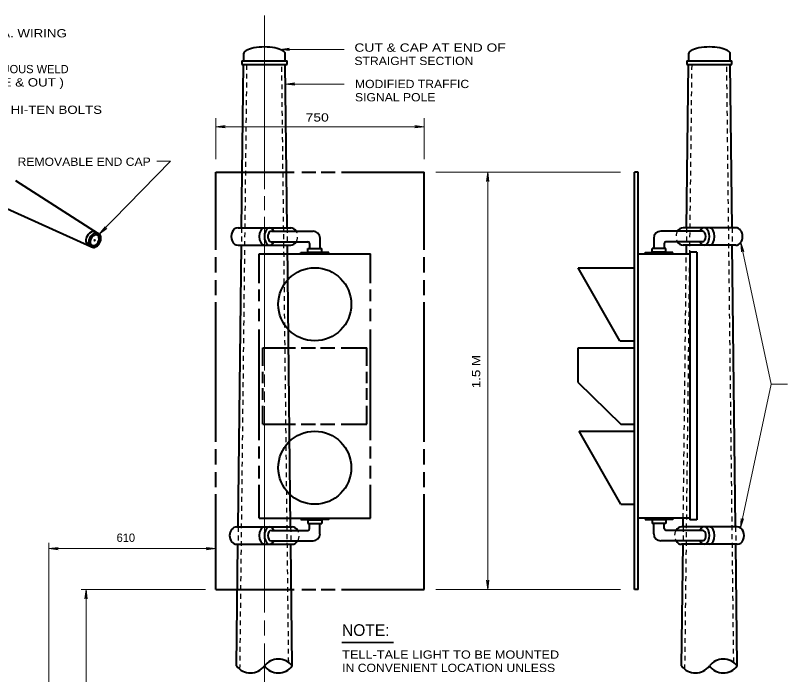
# Model space of a CAD drawing. Extents: x 312583 to 312854, y 144419 to 144597.
# Drawn here: x 312673.4 to 312744.4, y 144484.2 to 144544.7 of the extents above; entities that cross this region are included whole.
import ezdxf
from ezdxf.enums import TextEntityAlignment as Align

# ---------------------------------------------------------------- set-up
doc = ezdxf.new("R2010")
doc.units = 0
doc.header["$LTSCALE"] = 0.3
doc.header["$PDMODE"] = 32
doc.header["$PDSIZE"] = 0.15
doc.linetypes.add('SHORT_DASHED', pattern=[2.7, 1.5, -1.2])
doc.layers.add('1', color=7, linetype='Continuous', lineweight=40)
doc.layers.add('2', color=7, linetype='Continuous', lineweight=13)

msp = doc.modelspace()

# ---------------------------------------------------------------- linework, layer by layer
at = {"layer": '1', "lineweight": 13}
for p, q in [((312696.2997, 144544.7226), (312696.2997, 144528.7529)), ((312696.2997, 144528.1243), (312696.2997, 144526.8516)), ((312696.2997, 144526.2153), (312696.2997, 144512.1009)), ((312696.2997, 144511.7329), (312696.2997, 144510.6136)), ((312696.2997, 144510.1843), (312696.2997, 144509.2106)), ((312696.2997, 144508.8196), (312696.2997, 144489.8829)), ((312696.2997, 144489.1469), (312696.2997, 144487.7593)), ((312696.2997, 144487.0309), (312696.2997, 144467.6036))]:
    msp.add_line(p, q, dxfattribs=at)
at = {"layer": '1', "linetype": 'SHORT_DASHED', "lineweight": 25}
for p, q in [((312694.0533, 144484.6543), (312694.6973, 144540.2299)), ((312698.5307, 144485.2906), (312697.8943, 144540.2299)), ((312734.9397, 144484.6543), (312735.5913, 144540.2299)), ((312739.4247, 144485.2906), (312738.7807, 144540.2299)), ((312694.2067, 144525.2186), (312694.1913, 144523.6239)), ((312698.385, 144525.2186), (312698.408, 144523.6239)), ((312735.093, 144525.2186), (312735.0777, 144523.6239)), ((312739.279, 144525.2186), (312739.2943, 144523.6239)), ((312734.7863, 144498.5463), (312735.07, 144522.8189)), ((312693.8923, 144497.7489), (312693.8693, 144496.1466)), ((312698.707, 144497.7489), (312698.7223, 144496.1466)), ((312734.7787, 144497.7489), (312734.7633, 144496.1466)), ((312739.5933, 144497.7489), (312739.6163, 144496.1466))]:
    msp.add_line(p, q, dxfattribs=at)
at = {"layer": '1'}
for p, q in [((312694.2067, 144525.2186), (312694.383, 144540.2299)), ((312694.222, 144540.5519), (312698.3773, 144540.5519)), ((312694.222, 144540.2299), (312698.3773, 144540.2299)), ((312698.385, 144525.2186), (312698.2163, 144540.2299)), ((312735.093, 144525.2186), (312735.2693, 144540.2299)), ((312735.1083, 144540.5519), (312739.2637, 144540.5519)), ((312735.1083, 144540.2299), (312739.2637, 144540.2299)), ((312739.279, 144525.2186), (312739.1027, 144540.2299)), ((312691.8223, 144523.1793), (312691.8223, 144530.3323)), ((312691.8223, 144530.3323), (312699.0367, 144530.3323)), ((312699.7343, 144530.3323), (312701.0223, 144530.3323)), ((312701.513, 144530.3323), (312702.801, 144530.3323)), ((312703.3913, 144530.3323), (312710.989, 144530.3323)), ((312710.989, 144523.1793), (312710.989, 144530.3323)), ((312730.3167, 144491.9989), (312730.3167, 144530.3323)), ((312730.6387, 144530.3323), (312730.3167, 144530.3323)), ((312730.3167, 144491.9989), (312730.3167, 144530.3323)), ((312730.6387, 144491.9989), (312730.6387, 144530.3323)), ((312673.4223, 144529.5579), (312681.0353, 144524.6819)), ((312671.9733, 144527.2656), (312680.3377, 144523.5013)), ((312693.877, 144525.2186), (312698.7147, 144525.2186)), ((312696.936, 144524.8966), (312700.7693, 144524.8966)), ((312736.5497, 144524.8966), (312732.7163, 144524.8966)), ((312739.6087, 144525.2186), (312734.771, 144525.2186)), ((312696.936, 144523.9383), (312700.294, 144523.9383)), ((312701.4057, 144524.2603), (312701.4057, 144523.3019)), ((312732.0723, 144524.2603), (312732.0723, 144523.3019)), ((312736.5497, 144523.9383), (312733.1917, 144523.9383)), ((312693.877, 144523.6239), (312698.7147, 144523.6239)), ((312693.8923, 144497.7489), (312694.1913, 144523.6239)), ((312698.707, 144497.7489), (312698.408, 144523.6239)), ((312700.294, 144523.3019), (312701.5667, 144523.3019)), ((312700.294, 144522.9799), (312700.294, 144523.3019)), ((312700.4473, 144523.7773), (312700.4473, 144523.3019)), ((312701.5667, 144522.9799), (312701.5667, 144523.3019)), ((312733.1917, 144523.3019), (312731.919, 144523.3019)), ((312731.919, 144522.9799), (312731.919, 144523.3019)), ((312733.0307, 144523.7773), (312733.0307, 144523.3019)), ((312733.1917, 144522.9799), (312733.1917, 144523.3019)), ((312739.6087, 144523.6239), (312734.771, 144523.6239)), ((312735.07, 144522.8189), (312735.0777, 144523.6239)), ((312739.5933, 144497.7489), (312739.2943, 144523.6239)), ((312691.8223, 144521.1169), (312691.8223, 144522.5199)), ((312695.8167, 144522.8189), (312706.044, 144522.8189)), ((312695.8167, 144520.1356), (312695.8167, 144522.8189)), ((312699.65, 144522.9416), (312700.248, 144522.9416)), ((312699.65, 144522.8189), (312699.65, 144522.9416)), ((312700.294, 144522.9799), (312701.5667, 144522.9799)), ((312702.2107, 144522.9416), (312701.605, 144522.9416)), ((312702.2107, 144522.8189), (312702.2107, 144522.9416)), ((312706.044, 144520.1356), (312706.044, 144522.8189)), ((312710.989, 144521.1169), (312710.989, 144522.5199)), ((312730.6387, 144522.8189), (312735.3843, 144522.8189)), ((312731.275, 144522.9416), (312731.873, 144522.9416)), ((312731.275, 144522.8189), (312731.275, 144522.9416)), ((312733.1917, 144522.9799), (312731.919, 144522.9799)), ((312733.8357, 144522.9416), (312733.23, 144522.9416)), ((312733.8357, 144522.8189), (312733.8357, 144522.9416)), ((312735.3843, 144522.9799), (312735.3843, 144498.3853)), ((312736.0283, 144522.9799), (312735.3843, 144522.9799)), ((312736.0283, 144522.9799), (312736.0283, 144498.3853)), ((312725.134, 144521.5463), (312730.2477, 144521.5463)), ((312728.9673, 144514.8379), (312725.134, 144521.5463)), ((312691.8223, 144519.0393), (312691.8223, 144520.4193)), ((312710.989, 144519.0393), (312710.989, 144520.4193)), ((312695.8167, 144518.4643), (312695.8167, 144519.5453)), ((312706.044, 144518.4643), (312706.044, 144519.5453)), ((312691.8223, 144505.5459), (312691.8223, 144518.3723)), ((312710.989, 144505.5459), (312710.989, 144518.3723)), ((312695.8167, 144516.6396), (312695.8167, 144517.7666)), ((312706.044, 144516.6396), (312706.044, 144517.7666)), ((312695.8167, 144505.7069), (312695.8167, 144515.8806)), ((312706.044, 144505.7069), (312706.044, 144515.8806)), ((312728.9673, 144514.8379), (312730.2477, 144514.8379)), ((312696.1387, 144514.1939), (312699.1517, 144514.1939)), ((312696.1387, 144512.5456), (312696.1387, 144514.1939)), ((312699.6883, 144514.1939), (312700.984, 144514.1939)), ((312701.467, 144514.1939), (312702.755, 144514.1939)), ((312703.353, 144514.1939), (312705.722, 144514.1939)), ((312705.722, 144512.5456), (312705.722, 144514.1939)), ((312725.134, 144514.1939), (312730.2477, 144514.1939)), ((312725.134, 144511.0046), (312725.134, 144514.1939)), ((312696.1387, 144510.9356), (312696.1387, 144511.9783)), ((312705.722, 144510.9356), (312705.722, 144511.9783)), ((312696.1387, 144509.4023), (312696.1387, 144510.4909)), ((312705.722, 144509.4023), (312705.722, 144510.4909)), ((312725.134, 144511.0046), (312729.044, 144507.1713)), ((312696.1387, 144507.1713), (312696.1387, 144508.8503)), ((312705.722, 144507.1713), (312705.722, 144508.8503)), ((312696.1387, 144507.1713), (312699.1517, 144507.1713)), ((312699.6883, 144507.1713), (312700.984, 144507.1713)), ((312701.467, 144507.1713), (312702.755, 144507.1713)), ((312703.353, 144507.1713), (312705.722, 144507.1713)), ((312729.044, 144507.1713), (312730.3167, 144507.1713)), ((312725.2107, 144506.5273), (312730.3167, 144506.5273)), ((312729.044, 144499.8189), (312725.2107, 144506.5273)), ((312691.8223, 144503.4836), (312691.8223, 144504.8866)), ((312695.8167, 144504.0356), (312695.8167, 144505.1166)), ((312706.044, 144504.0356), (312706.044, 144505.1166)), ((312710.989, 144503.4836), (312710.989, 144504.8866)), ((312695.8167, 144502.2033), (312695.8167, 144503.3379)), ((312706.044, 144502.2033), (312706.044, 144503.3379)), ((312691.8223, 144501.4059), (312691.8223, 144502.7859)), ((312710.989, 144501.4059), (312710.989, 144502.7859)), ((312695.8167, 144498.5463), (312695.8167, 144501.6129)), ((312706.044, 144498.5463), (312706.044, 144501.6129)), ((312691.8223, 144491.9989), (312691.8223, 144500.7389)), ((312710.989, 144491.9989), (312710.989, 144500.7389)), ((312729.044, 144499.8189), (312730.3167, 144499.8189)), ((312695.8167, 144498.5463), (312706.044, 144498.5463)), ((312699.65, 144498.5463), (312699.65, 144498.4236)), ((312699.65, 144498.4236), (312700.248, 144498.4236)), ((312700.294, 144498.3853), (312701.5667, 144498.3853)), ((312700.294, 144498.3853), (312700.294, 144498.0633)), ((312701.5667, 144498.3853), (312701.5667, 144498.0633)), ((312702.2107, 144498.4236), (312701.605, 144498.4236)), ((312702.2107, 144498.5463), (312702.2107, 144498.4236)), ((312735.3843, 144498.5463), (312730.6387, 144498.5463)), ((312731.275, 144498.5463), (312731.275, 144498.4236)), ((312731.275, 144498.4236), (312731.873, 144498.4236)), ((312733.1917, 144498.3853), (312731.919, 144498.3853)), ((312731.919, 144498.3853), (312731.919, 144498.0633)), ((312733.1917, 144498.3853), (312733.1917, 144498.0633)), ((312733.8357, 144498.4236), (312733.23, 144498.4236)), ((312733.8357, 144498.5463), (312733.8357, 144498.4236)), ((312734.7787, 144497.7489), (312734.7863, 144498.5463)), ((312736.0283, 144498.3853), (312735.3843, 144498.3853)), ((312693.739, 144497.7489), (312698.8527, 144497.7489)), ((312700.294, 144498.0633), (312701.5667, 144498.0633)), ((312700.4473, 144497.5879), (312700.4473, 144498.0633)), ((312701.4057, 144497.1049), (312701.4057, 144498.0633)), ((312733.1917, 144498.0633), (312731.919, 144498.0633)), ((312732.0723, 144497.1049), (312732.0723, 144498.0633)), ((312733.0307, 144497.5879), (312733.0307, 144498.0633)), ((312739.739, 144497.7489), (312734.633, 144497.7489)), ((312696.936, 144497.4269), (312700.294, 144497.4269)), ((312736.5497, 144497.4269), (312733.1917, 144497.4269)), ((312696.936, 144496.4686), (312700.7693, 144496.4686)), ((312736.5497, 144496.4686), (312732.7163, 144496.4686)), ((312693.739, 144496.1466), (312698.8527, 144496.1466)), ((312693.739, 144484.9686), (312693.8693, 144496.1466)), ((312698.8527, 144484.9686), (312698.7223, 144496.1466)), ((312739.739, 144496.1466), (312734.633, 144496.1466)), ((312734.633, 144484.9686), (312734.7633, 144496.1466)), ((312739.739, 144484.9686), (312739.6163, 144496.1466)), ((312691.8223, 144491.9989), (312699.0367, 144491.9989)), ((312699.7343, 144491.9989), (312701.0223, 144491.9989)), ((312701.513, 144491.9989), (312702.801, 144491.9989)), ((312703.3913, 144491.9989), (312710.989, 144491.9989)), ((312730.6387, 144491.9989), (312730.3167, 144491.9989))]:
    msp.add_line(p, q, dxfattribs=at)
for centre in [(312700.9291, 144518.1895), (312700.9291, 144503.1757)]:
    msp.add_circle(centre, 3.3542, dxfattribs=at)
for centre, radius, start, end in [((312700.7693, 144524.259), 0.6389, 0, 90), ((312732.7138, 144524.259), 0.6389, 90, 180), ((312700.2902, 144523.7798), 0.1597, 0, 90), ((312733.1929, 144523.7798), 0.1597, 90, 180), ((312700.2502, 144522.9809), 0.0399, 270, 0), ((312701.6079, 144522.9809), 0.0399, 180, 270), ((312731.8752, 144522.9809), 0.0399, 270, 0), ((312733.2329, 144522.9809), 0.0399, 180, 270), ((312700.2502, 144498.3843), 0.0399, 0, 90), ((312701.6079, 144498.3843), 0.0399, 90, 180), ((312731.8752, 144498.3843), 0.0399, 0, 90), ((312733.2329, 144498.3843), 0.0399, 90, 180), ((312700.2902, 144497.5854), 0.1597, 270, 0), ((312700.7693, 144497.1062), 0.6389, 270, 0), ((312732.7138, 144497.1062), 0.6389, 180, 270), ((312733.1929, 144497.5854), 0.1597, 180, 270), ((312697.5749, 144484.009), 1.5972, 36.8699, 143.1301), ((312738.4638, 144484.009), 1.5972, 36.8699, 143.1301), ((312695.0193, 144485.9257), 1.5972, 216.8699, 323.1301), ((312697.5749, 144485.9257), 1.5972, 216.8699, 323.1301), ((312735.9082, 144485.9257), 1.5972, 216.8699, 323.1301), ((312738.4638, 144485.9257), 1.5972, 216.8699, 323.1301)]:
    msp.add_arc(centre, radius, start, end, dxfattribs=at)
for centre, major_axis, ratio, start_param, end_param in [((312696.2971, 144541.1895), (1.9167, 0), 0.333333, 6.2831853, 9.424778), ((312737.186, 144541.1895), (1.9167, 0), 0.333333, 6.2831853, 9.424778), ((312696.7763, 144524.4187), (0, -0.7986), 0.6, 2.2142974, 7.2104805), ((312736.7068, 144524.4187), (0, 0.7986), 0.6, 2.2142974, 7.2104805), ((312693.8776, 144524.4174), (0, 0.7986), 0.8, 6.2831853, 9.424778), ((312696.2971, 144524.4187), (0, -0.7986), 0.6, 3.1415927, 6.2831853), ((312696.936, 144524.4187), (0, 0.4792), 0.666667, 6.2831853, 9.424778), ((312698.7159, 144524.4174), (0, 0.7986), 0.8, 5.359754, 6.2831853), ((312734.7672, 144524.4174), (0, 0.7986), 0.8, 6.2831853, 7.2066166), ((312736.5471, 144524.4187), (0, 0.4792), 0.666667, 3.1415927, 6.2831853), ((312737.186, 144524.4187), (0, 0.7986), 0.6, 3.1415927, 6.2831853), ((312739.6055, 144524.4174), (0, 0.7986), 0.8, 3.1415927, 6.2831853), ((312698.7159, 144524.4174), (0, 0.7986), 0.8, 3.1415927, 4.0688879), ((312734.7672, 144524.4174), (0, 0.7986), 0.8, 2.2142974, 3.1415927), ((312693.7416, 144496.9465), (0, -0.7986), 0.8, 3.1415927, 6.2831853), ((312696.2971, 144496.9465), (0, -0.7986), 0.6, 3.1415927, 6.2831853), ((312696.7763, 144496.9465), (0, -0.7986), 0.6, 2.2142974, 7.2104805), ((312698.8527, 144496.9465), (0, -0.7986), 0.8, 2.2142974, 3.1415927), ((312734.6304, 144496.9465), (0, -0.7986), 0.8, 3.1415927, 4.0688879), ((312736.7068, 144496.9465), (0, 0.7986), 0.6, 2.2142974, 7.2104805), ((312737.186, 144496.9465), (0, 0.7986), 0.6, 3.1415927, 6.2831853), ((312739.7416, 144496.9465), (0, -0.7986), 0.8, 6.2831853, 9.424778), ((312696.936, 144496.9465), (0, -0.4792), 0.666667, 3.1415927, 6.2831853), ((312736.5471, 144496.9465), (0, -0.4792), 0.666667, 6.2831853, 9.424778), ((312698.8527, 144496.9465), (0, -0.7986), 0.8, 6.2831853, 7.2066166), ((312734.6304, 144496.9465), (0, -0.7986), 0.8, 5.359754, 6.2831853)]:
    msp.add_ellipse(centre, major_axis=major_axis, ratio=ratio, start_param=start_param, end_param=end_param, dxfattribs=at)
at = {"layer": '1', "linetype": 'SHORT_DASHED', "lineweight": 25}
for centre, major_axis, start_param, end_param in [((312698.7159, 144524.4174), (0, 0.7986), 4.0688879, 5.3508901), ((312734.7672, 144524.4174), (0, 0.7986), 0.9322952, 2.2142974), ((312698.8527, 144496.9465), (0, -0.7986), 0.9322952, 2.2142974), ((312734.6304, 144496.9465), (0, -0.7986), 4.0688879, 5.3508901)]:
    msp.add_ellipse(centre, major_axis=major_axis, ratio=0.8, start_param=start_param, end_param=end_param, dxfattribs=at)
at = {"layer": '2'}
for p, q in [((312697.741, 144541.6099), (312698.6073, 144541.7173)), ((312697.741, 144541.6099), (312703.6213, 144541.6099)), ((312697.741, 144541.6099), (312698.6073, 144541.5026)), ((312698.6073, 144541.7173), (312698.3313, 144541.6099)), ((312698.6073, 144541.5026), (312698.3313, 144541.6099)), ((312698.2317, 144538.4206), (312699.098, 144538.5279)), ((312698.2317, 144538.4206), (312703.6213, 144538.4206)), ((312698.2317, 144538.4206), (312699.098, 144538.3133)), ((312699.098, 144538.5279), (312698.822, 144538.4206)), ((312699.098, 144538.3133), (312698.822, 144538.4206)), ((312691.8223, 144531.5359), (312691.8223, 144535.3003)), ((312710.989, 144531.5359), (312710.989, 144535.3003)), ((312691.8223, 144534.4953), (312692.6887, 144534.6026)), ((312691.8223, 144534.4953), (312710.989, 144534.4953)), ((312691.8223, 144534.4953), (312692.6887, 144534.3879)), ((312692.6887, 144534.6026), (312692.4127, 144534.4953)), ((312692.6887, 144534.3879), (312692.4127, 144534.4953)), ((312710.1227, 144534.6026), (312710.3987, 144534.4953)), ((312710.989, 144534.4953), (312710.1227, 144534.6026)), ((312710.1227, 144534.3879), (312710.3987, 144534.4953)), ((312710.989, 144534.4953), (312710.1227, 144534.3879)), ((312712.047, 144530.3323), (312729.0057, 144530.3323)), ((312716.8233, 144530.3323), (312716.716, 144529.4659)), ((312716.8233, 144491.9989), (312716.8233, 144530.3323)), ((312716.8233, 144530.3323), (312716.9307, 144529.4659)), ((312716.716, 144529.4659), (312716.8233, 144529.7419)), ((312716.9307, 144529.4659), (312716.8233, 144529.7419)), ((312681.1273, 144524.6206), (312681.6563, 144525.3106)), ((312681.6563, 144525.3106), (312681.5413, 144525.0423)), ((312681.1273, 144524.6206), (312681.8097, 144525.1649)), ((312681.8097, 144525.1649), (312681.5413, 144525.0423)), ((312740.0687, 144523.8693), (312740.1453, 144523.0029)), ((312740.0687, 144523.8693), (312740.36, 144523.0489)), ((312740.1453, 144523.0029), (312740.1913, 144523.2943)), ((312740.36, 144523.0489), (312740.1913, 144523.2943)), ((312740.038, 144497.6569), (312742.8517, 144510.8436)), ((312740.038, 144497.6569), (312740.1147, 144498.5233)), ((312740.038, 144497.6569), (312740.3217, 144498.4773)), ((312740.1147, 144498.5233), (312740.1607, 144498.2319)), ((312740.3217, 144498.4773), (312740.1607, 144498.2319)), ((312676.489, 144460.8033), (312676.489, 144496.2769)), ((312676.489, 144495.7479), (312677.3553, 144495.8553)), ((312676.489, 144495.7479), (312691.8223, 144495.7479)), ((312676.489, 144495.7479), (312677.3553, 144495.6406)), ((312677.3553, 144495.8553), (312677.0793, 144495.7479)), ((312677.3553, 144495.6406), (312677.0793, 144495.7479)), ((312690.956, 144495.8553), (312691.232, 144495.7479)), ((312691.8223, 144495.7479), (312690.956, 144495.8553)), ((312690.956, 144495.6406), (312691.232, 144495.7479)), ((312691.8223, 144495.7479), (312690.956, 144495.6406)), ((312716.716, 144492.8653), (312716.8233, 144492.5893)), ((312716.8233, 144491.9989), (312716.716, 144492.8653)), ((312716.9307, 144492.8653), (312716.8233, 144492.5893)), ((312716.8233, 144491.9989), (312716.9307, 144492.8653)), ((312679.456, 144491.9989), (312690.8793, 144491.9989)), ((312679.916, 144491.9989), (312679.8087, 144491.1326)), ((312679.916, 144461.9686), (312679.916, 144491.9989)), ((312679.916, 144491.9989), (312680.0233, 144491.1326)), ((312712.047, 144491.9989), (312729.0057, 144491.9989)), ((312679.8087, 144491.1326), (312679.916, 144491.4086)), ((312680.0233, 144491.1326), (312679.916, 144491.4086))]:
    msp.add_line(p, q, dxfattribs=at)
at = {"layer": '2', "lineweight": 40}
for p, q in [((312694.383, 144541.1883), (312694.383, 144540.5519)), ((312698.2163, 144540.5519), (312698.2163, 144541.1883)), ((312735.2693, 144541.1883), (312735.2693, 144540.5519)), ((312739.1027, 144540.5519), (312739.1027, 144541.1883)), ((312694.222, 144540.5519), (312694.222, 144540.2299)), ((312698.3773, 144540.2299), (312698.3773, 144540.5519)), ((312735.1083, 144540.5519), (312735.1083, 144540.2299)), ((312739.2637, 144540.2299), (312739.2637, 144540.5519))]:
    msp.add_line(p, q, dxfattribs=at)
at = {"layer": '2', "lineweight": 35}
msp.add_line((312703.4067, 144487.1306), (312708.1677, 144487.1306), dxfattribs=at)
at = {"layer": '2'}
for points in [[(312686.4097, 144531.3289), (312687.6593, 144531.3289), (312681.1273, 144524.6206)], [(312740.0687, 144523.8693), (312742.8517, 144510.8436), (312744.3697, 144510.8436)]]:
    msp.add_lwpolyline(points, dxfattribs=at)
at = {"layer": '2', "lineweight": 40}
for centre, radius, start, end in [((312680.8414, 144524.3117), 0.4185, 10.24027, 62.85741), ((312680.4388, 144524.2174), 0.672, 291.53281, 11.68964), ((312680.4388, 144524.2174), 0.8317, 288.29849, 11.70296), ((312680.8414, 144524.3117), 0.2587, 10.30163, 67.69971), ((312680.6064, 144523.905), 0.4879, 236.32883, 280.89953), ((312680.6092, 144523.9688), 0.3838, 239.92015, 281.42077)]:
    msp.add_arc(centre, radius, start, end, dxfattribs=at)
for centre, major_axis, ratio, start_param, end_param in [((312680.4622, 144524.2149), (0.329, 0.6248), 0.740902, 6.2831853, 9.424778), ((312680.6836, 144524.0906), (-0.3479, -0.5919), 0.716654, 3.1415927, 6.2831853), ((312680.6836, 144524.0906), (-0.2669, -0.4542), 0.630755, 3.1796136, 6.3769681)]:
    msp.add_ellipse(centre, major_axis=major_axis, ratio=ratio, start_param=start_param, end_param=end_param, dxfattribs=at)
at = {"layer": '2'}
for p in [(312680.698, 144524.0686), (312680.698, 144523.4246)]:
    msp.add_point(p, dxfattribs=at)

# ---------------------------------------------------------------- texts
for s, width, p in [('64 MM DIA. WIRING', 1.2, (312666.829, 144542.7053)), ('CUT & CAP AT END OF', 1.25, (312704.5682, 144541.3885)), ('STRAIGHT SECTION', 1.1, (312704.5682, 144540.1685)), ('( INSIDE & OUT )', 1.2, (312668.255, 144538.1963)), ('MODIFIED TRAFFIC', 1.1, (312704.6201, 144538.0497)), ('SIGNAL POLE', 1.1, (312704.6201, 144536.8297)), ('(4) M30 HI-TEN BOLTS', 1.2, (312668.4337, 144535.6808)), ('750 ', 1.25, (312700.0917, 144534.9755)), ('REMOVABLE END CAP', 1.1, (312673.6144, 144530.9063)), ('TELL-TALE LIGHT TO BE MOUNTED', 1.15, (312703.445, 144485.6346)), ('IN CONVENIENT LOCATION UNLESS', 1.1, (312703.445, 144484.4146))]:
    msp.add_text(s, height=0.76, dxfattribs=dict(at, width=width)).set_placement(p)
for s, p in [('CONTINUOUS WELD', (312668.255, 144539.4163)), ('610', (312682.7161, 144496.3699))]:
    msp.add_text(s, height=0.76, dxfattribs=at).set_placement(p)
at = {"layer": '2', "width": 1.2}
msp.add_text('1.5 M', height=0.76, rotation=90, dxfattribs=at).set_placement((312716.1311, 144510.4861))
at = {"layer": '2'}
msp.add_text('NOTE:', height=1.07, dxfattribs=at).set_placement((312705.6095, 144487.7322), align=Align.CENTER)

doc.saveas('drawing.dxf')
